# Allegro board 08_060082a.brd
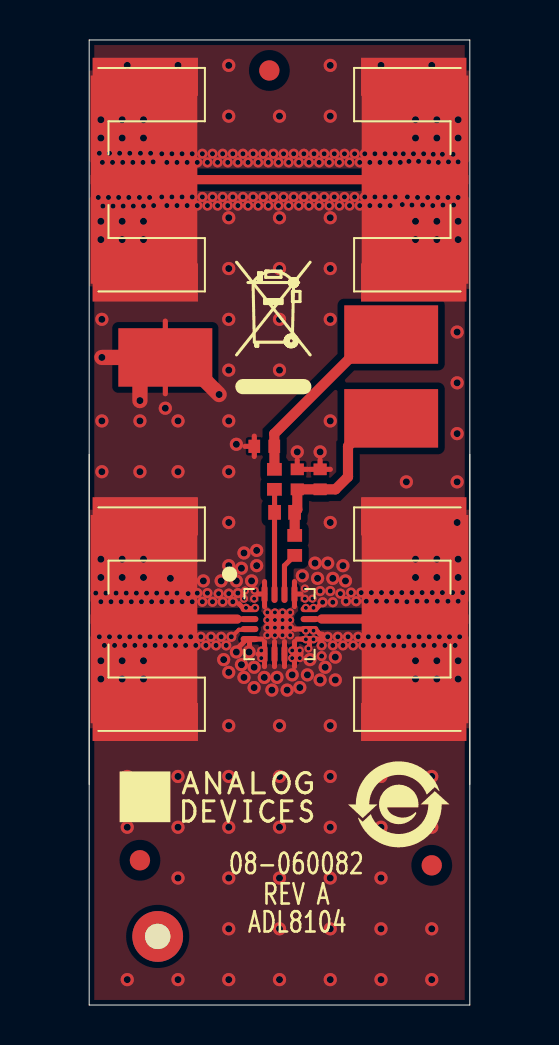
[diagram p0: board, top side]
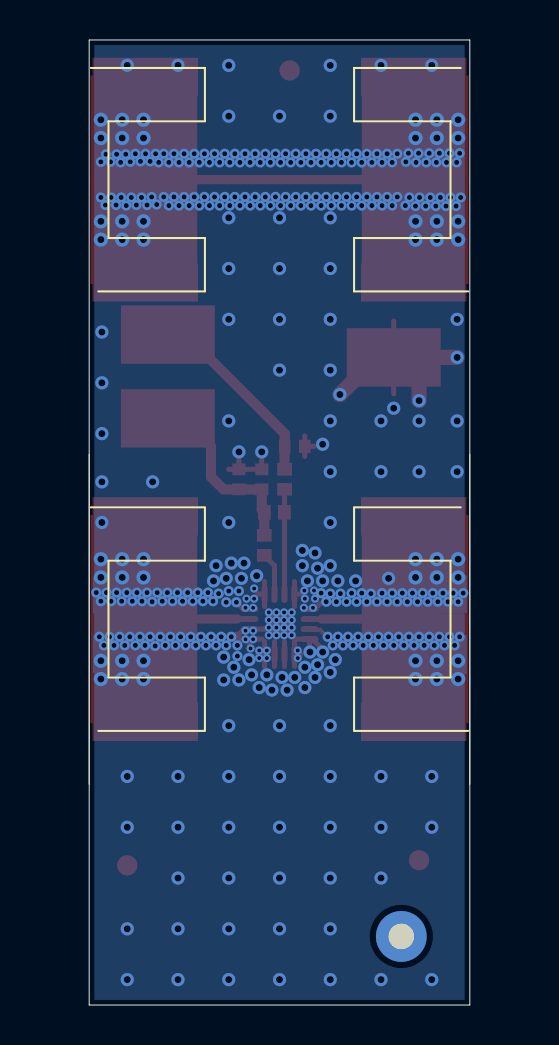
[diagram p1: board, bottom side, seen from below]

Outline 19.05 x 48.26 mm; copper layers: TOP, L2_GND, L3_GND, BOTTOM. Coordinates in mm from the lower left corner of the outline.
Outline path: 0,48.26 19.05,48.26 19.05,0 0,0 0,48.26

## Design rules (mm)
constraint set DEFAULT: min track width 0.254

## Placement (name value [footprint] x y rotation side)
C1  1000PF  [C0402]  11.56 26.29 90 top
C2  1uF  [C0402]  10.41 26.29 90 top
C3  1000PF  [C0402]  8.76 27.94 0 top
DUT1  GEN_QFN16_3x3_PAD1_1x1_1  [QFN16_3X3_PAD1_1X1_1]  9.53 19.05 270 top
GND  5016  [CNKEY5016TP]  3.81 32.39 0 top
J1  142-0701-851  [CNSMA10G62THK_EDGE]  0 41.28 180 top
J2  142-0701-851  [CNSMA10G62THK_EDGE]  19.05 41.28 0 top
NOREF  -  []  -219.07 -158.75 0 top
NOREF#2  -  []  0 0 0 top
NOREF#3  -  [unnamed#2]  9.02 46.74 0 top
NOREF#4  -  []  9.02 30.61 0 top
NOREF#5  -  []  161.93 69.85 0 top
NOREF#6  -  []  63.5 63.5 0 top
NOREF#7  -  [unnamed#2]  17.15 6.99 0 top
NOREF#8  -  []  -219.07 -158.75 0 top
NOREF#9  -  []  -89.66 126.66 0 top
NOREF#10  -  []  0 18.92 0 top
NOREF#11  -  []  -269.88 -336.55 0 top
NOREF#12  -  []  -192.3 79.27 0 top
NOREF#13  -  []  -269.88 -336.55 0 top
NOREF#14  -  [unnamed#2]  3.43 3.43 0 top
NOREF#15  -  []  12.32 61.09 0 top
NOREF#16  -  []  0 0 0 top
NOREF#17  -  []  19.05 0 90 top
NOREF#18  -  []  -99.9 133.05 0 top
NOREF#19  -  []  0 0 90 top
NOREF#20  -  []  -203.45 -70.99 0 top
NOREF#21  -  []  0 0 0 top
NOREF#22  -  [unnamed#2]  2.54 7.24 0 top
NOREF#23  -  []  52.7 -150.24 0 top
NOREF#24  -  []  0 48.26 270 top
NOREF#25  -  []  1.52 9.14 0 top
NOREF#26  -  []  19.05 0 90 top
NOREF#27  -  []  19.05 48.26 180 top
NOREF#28  -  []  15.49 10.03 0 top
NOREF#29  -  []  170.94 43.43 180 bottom
R1  0  [R0402]  9.27 26.29 270 top
R2  0  [R0402]  9.78 24.64 0 top
R4  0  [R0402]  10.29 22.99 270 top
RFIN  142-0701-851  [CNSMA10G62THK_EDGE]  0 19.3 180 top
RFOUT  142-0701-851  [CNSMA10G62THK_EDGE]  19.05 19.3 0 top
VBIAS  5016  [CNKEY5016TP]  15.11 33.53 0 top
VDD  5016  [CNKEY5016TP]  15.11 29.34 0 top

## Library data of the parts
C1 C3 = CAP: User Part Number: UPN; Tolerance: 10; alternate symbols: (); part number: CAP_SM-1000PF,25V,10,E025706,C0402; tolerance: 10
C2 = CAP: User Part Number: UPN; Tolerance: 10; alternate symbols: (); part number: CAP_SM-1UF,6.3V,10,E011561,C0402; tolerance: 10
DUT1 = GEN16P_SQ_PAD: User Part Number: UPN; Tolerance: N/A; alternate symbols: (); part number: GEN16P_SQ_PAD_SM-GEN_QFN16_3X3_PAD1_1X1_1,E007588,QFN16_3X3_PAD1_1X1_1; tolerance: N/A
GND VBIAS VDD = CNTP1P: alternate symbols: (); part number: CNTP1P_SM-5016,E005890,CNKEY5016TP; tolerance: N/A
J1 J2 RFIN RFOUT = CNBNC4P: User Part Number: UPN; Tolerance: N/A; alternate symbols: (CNSMA10G30THK_EDGE,CNSMA10G10THK_EDGE,CNSMAL562W375H166_HFSS); part number: CNBNC4P_SM-142-0701-851,E029168,CNSMA10G62THK_EDGE; tolerance: N/A
R1 R2 R4 = RES: User Part Number: UPN; Tolerance: 1; alternate symbols: (R0402L); part number: RES_SM-0,E010661,1/16W,1,R0402; tolerance: 1

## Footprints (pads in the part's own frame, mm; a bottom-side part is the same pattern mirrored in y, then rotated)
C0402
  rect 0.584x0.66 smd: 1(-0.5,0) 2(0.5,0)
CNKEY5016TP
  rect 4.699x2.921 smd: 1(0,0)
CNSMA10G62THK_EDGE
  rect 2.349x0.457 smd: 1(-1.252,0)
  custom 0.921x0.921 smd: 2(-2.807,-4.255) 3(-2.807,4.255)
  rect 5.334x10.414 smd: 4(-2.743,0)
QFN16_3X3_PAD1_1X1_1
  oval 0.305x0.889 smd: 1(-0.749,-1.501) 2(-0.249,-1.501) 3(0.249,-1.501) 4(0.749,-1.501) 9(0.749,1.501) 10(0.249,1.501) 11(-0.249,1.501) 12(-0.749,1.501)
  oval 0.889x0.305 smd: 5(1.501,-0.749) 6(1.501,-0.249) 7(1.501,0.249) 8(1.501,0.749) 13(-1.501,0.749) 14(-1.501,0.249) 15(-1.501,-0.249) 16(-1.501,-0.749)
  rect 1.092x1.092 smd: PAD(0,0)
R0402
  rect 0.635x0.737 smd: 1(-0.5,0) 2(0.5,0)
unnamed#2
  round 1.016 smd: (0,0)

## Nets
GND: C1.2(N2) C2.2(N2) C3.1 DUT1.1 DUT1.3 DUT1.4 DUT1.5 DUT1.6 DUT1.7 DUT1.8 DUT1.9 DUT1.10 DUT1.12 DUT1.13 DUT1.16 DUT1.PAD GND.1(N1) J1.2 J1.3 J1.4(SH3) J2.2 J2.3 J2.4(SH3) RFIN.2 RFIN.3 RFIN.4(SH3) RFOUT.2 RFOUT.3 RFOUT.4(SH3)
UNNAMED_3_CAP_I190_N1: C1.1 C2.1 R2.2(N2) R4.1 VDD.1(N1)
UNNAMED_3_CAP_I214_N2: C3.2(N2) R1.1 VBIAS.1(N1)
UNNAMED_3_CNBNC4P_I227_CNTR: DUT1.2 RFIN.1
UNNAMED_3_CNBNC4P_I228_CNTR: J1.1 J2.1
UNNAMED_3_CNBNC4P_I232_CNTR: DUT1.11 RFOUT.1
UNNAMED_3_GEN16PSQPAD_I213_N14: DUT1.14 R4.2(N2)
UNNAMED_3_GEN16PSQPAD_I213_N15: DUT1.15 R1.2(N2) R2.1

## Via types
v1: diameter 0.66, hole 0.356, TOP to BOTTOM, 116 vias
v2: diameter 0.711, hole 0.356, TOP to BOTTOM, 48 vias
v3: diameter 0.508, hole 0.254, TOP to BOTTOM, 257 vias
v4: diameter 0.406, hole 0.203, TOP to BOTTOM, 38 vias

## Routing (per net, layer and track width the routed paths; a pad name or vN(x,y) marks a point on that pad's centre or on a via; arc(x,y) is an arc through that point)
GND: length 33.2
  TOP w0.203: 7.13,18.41 7.49,18.77 7.99,18.77 DUT1.3
  TOP w0.254: 11.78,18.41 v3(11.94,18.41) ; DUT1.5 8.78,18.17 ; DUT1.5 8.78,16.92 ; DUT1.5 8.44,17.55 ; 8.02,17.97 DUT1.4 ; DUT1.4 8.65,18.3 ; DUT1.4 7.89,18.3 7.24,17.65 ; C1.2 11.56,27.26 ; C1.2 12.07,26.79 ; C1.2 11.05,26.79 ; 9.77,16.92 DUT1.7 9.77,18.17 ; 8.78,19.93 DUT1.16 ; DUT1.16 8.78,21.18 ; DUT1.16 8.44,20.55 ; DUT1.9 11.65,18.3 ; DUT1.9 10.4,18.3 ; DUT1.9 11.03,17.97 ; v3(11.68,20.14) 11.34,19.8 DUT1.12 ; 10.27,19.93 DUT1.13 ; DUT1.13 10.27,21.18 ; DUT1.13 10.61,20.55 ; 8.26,27.43 C3.1 ; C3.1 8.26,28.45 ; C3.1 7.79,27.94 ; DUT1.8 10.27,18.17 ; DUT1.8 10.27,16.92 ; DUT1.8 10.61,17.55 ; 10.29,18.8 10.29,18.8 DUT1.10 11.3,18.8 11.56,18.54 11.68,18.54 ; DUT1.1 7.76,19.8 7.49,20.07 ; 3.81,34.2 GND.1 3.81,30.57 ; 10.41,27.26 C2.2 10.92,26.79 ; 9.28,16.92 DUT1.6 9.28,18.17
  TOP w0.762: 2.54,32.39 GND.1 5.08,32.39 5.08,31.95 v1(6.5,30.53) ; 2.54,32.39 v1(2.54,30.23) ; 2.54,32.39 v1(0.64,32.39)
  vias: v1(0.64,34.29) v1(0.64,29.21) v1(0.64,26.67) v1(1.91,46.99) v1(1.91,11.43) v1(1.91,8.89) v1(1.91,1.27) v1(2.54,29.21) v1(2.54,26.67) v1(3.81,29.84) v1(4.06,21.34) v1(4.45,46.99) v1(4.45,29.21) v1(4.45,26.67) v1(4.45,11.43) v1(4.45,8.89) v1(4.45,6.35) v1(4.45,1.27) v1(5.72,21.21) v1(6.6,21.21) v1(6.73,17.27) v1(6.99,46.99) v1(6.99,44.45) v1(6.99,39.37) v1(6.99,36.83) v1(6.99,34.29) v1(6.99,31.75) v1(6.99,29.21) v1(6.99,26.67) v1(6.99,24.13) v1(6.99,21.97) v1(6.99,16.64) v1(6.99,13.97) v1(6.99,11.43) v1(6.99,8.89) v1(6.99,6.35) v1(6.99,3.81) v1(6.99,1.27) v1(7.37,28.04) v1(7.37,21.21) v1(7.37,17.65) v1(7.62,21.84) v1(7.62,17.02) v1(7.75,22.61) v1(7.75,16.38) v1(8,17.65) v1(8.13,21.21) v1(8.26,16.89) v1(8.26,15.88) v1(8.38,22.73) v1(8.38,21.97) v1(8.76,16.38) v1(9.14,15.75) v1(9.4,16.38) v1(9.53,44.45) v1(9.53,39.37) v1(9.53,36.83) v1(9.53,34.29) v1(9.53,31.75) v1(9.53,13.97) v1(9.53,11.43) v1(9.53,8.89) v1(9.53,6.35) v1(9.53,3.81) v1(9.53,1.27) v1(9.91,15.75) v1(10.16,16.51) v1(10.41,27.66) v1(10.54,15.88) v1(10.67,21.46) v1(10.92,16.51) v1(11.05,17.27) v1(11.3,22.1) v1(11.43,21.34) v1(11.56,27.66) v1(11.56,16.26) v1(11.81,16.89) v1(11.94,22.1) v1(12.07,46.99) v1(12.07,44.45) v1(12.07,39.37) v1(12.07,36.83) v1(12.07,34.29) v1(12.07,29.21) v1(12.07,24.13) v1(12.07,13.97) v1(12.07,11.43) v1(12.07,8.89) v1(12.07,6.35) v1(12.07,3.81) v1(12.07,1.27) v1(12.19,21.34) v1(12.32,17.4) v1(12.32,16.26) v1(12.7,21.97) v1(12.83,21.21) v1(14.61,46.99) v1(14.61,11.43) v1(14.61,8.89) v1(14.61,6.35) v1(14.61,3.81) v1(14.61,1.27) v1(15.88,26.16) v1(17.15,46.99) v1(17.15,11.43) v1(17.15,8.89) v1(17.15,3.81) v1(17.15,1.27) v1(18.42,33.66) v1(18.42,31.12) v1(18.42,28.58) v1(18.42,26.16) v1(18.42,24.13) v2(0.58,44.27) v2(0.58,43.36) v2(0.58,39.19) v2(0.58,38.28) v2(0.58,22.3) v2(0.58,21.38) v2(0.58,17.22) v2(0.58,16.3) v2(1.65,44.27) v2(1.65,43.36) v2(1.65,39.19) v2(1.65,38.28) v2(1.65,22.3) v2(1.65,21.38) v2(1.65,17.22) v2(1.65,16.3) v2(2.72,44.27) v2(2.72,43.36) v2(2.72,39.19) v2(2.72,38.28) v2(2.72,22.3) v2(2.72,21.38) v2(2.72,17.22) v2(2.72,16.3) v2(16.33,44.27) v2(16.33,43.36) v2(16.33,39.19) v2(16.33,38.28) v2(16.33,22.3) v2(16.33,21.38) v2(16.33,17.22) v2(16.33,16.3) v2(17.4,44.27) v2(17.4,43.36) v2(17.4,39.19) v2(17.4,38.28) v2(17.4,22.3) v2(17.4,21.38) v2(17.4,17.22) v2(17.4,16.3) v2(18.47,44.27) v2(18.47,43.36) v2(18.47,39.19) v2(18.47,38.28) v2(18.47,22.3) v2(18.47,21.38) v2(18.47,17.22) v2(18.47,16.3) v3(0.33,20.6) v3(0.46,40.39) v3(0.51,42.6) v3(0.51,18.41) v3(0.66,42.14) v3(0.58,20.17) v3(0.69,39.95) v3(0.76,17.98) v3(0.84,20.6) v3(0.97,40.39) v3(1.02,42.6) v3(1.02,18.41) v3(1.17,42.14) v3(1.09,20.17) v3(1.19,39.95) v3(1.27,17.98) v3(1.35,20.6) v3(1.47,40.39) v3(1.52,42.6) v3(1.52,18.41) v3(1.6,20.17) v3(1.68,42.14) v3(1.7,39.95) v3(1.85,20.6) v3(1.78,17.98) v3(2.03,42.6) v3(1.98,40.39) v3(2.03,18.41) v3(2.11,20.17) v3(2.18,42.14) v3(2.21,39.95) v3(2.36,20.6) v3(2.29,17.98) v3(2.57,42.6) v3(2.51,40.39) v3(2.54,18.41) v3(2.62,20.17) v3(2.69,42.14) v3(2.72,39.95) v3(2.87,20.6) v3(2.79,17.98) v3(3.07,42.6) v3(3.02,40.39) v3(3.05,18.41) v3(3.12,20.17) v3(3.2,42.16) v3(3.23,39.98) v3(3.3,17.98) v3(3.38,20.6) v3(3.56,18.41) v3(3.63,42.57) v3(3.63,40.41) v3(3.63,20.17) v3(3.81,17.98) v3(3.89,42.14) v3(3.89,39.98) v3(3.89,20.6) v3(4.06,18.41) v3(4.14,42.57) v3(4.14,40.41) v3(4.14,20.17) v3(4.32,17.98) v3(4.39,42.14) v3(4.39,39.98) v3(4.39,20.6) v3(4.57,18.41) v3(4.65,42.57) v3(4.65,40.41) v3(4.65,20.17) v3(4.83,17.98) v3(4.9,42.14) v3(4.9,39.98) v3(4.95,20.57) v3(5.16,42.57) v3(5.16,40.41) v3(5.16,20.17) v3(5.08,18.41) v3(5.33,17.98) v3(5.41,42.14) v3(5.41,39.98) v3(5.41,20.6) v3(5.66,42.57) v3(5.66,40.41) v3(5.66,20.17) v3(5.59,18.41) v3(5.84,17.98) v3(5.92,42.14) v3(5.92,39.98) v3(5.92,20.6) v3(6.17,42.57) v3(6.17,40.41) v3(6.17,20.17) v3(6.1,18.41) v3(6.35,17.98) v3(6.43,42.14) v3(6.43,39.98) v3(6.48,20.57) v3(6.6,18.41) v3(6.68,42.57) v3(6.68,40.41) v3(6.68,20.17) v3(6.86,17.98) v3(6.93,42.14) v3(6.93,39.98) v3(6.99,20.57) v3(7.11,18.41) v3(7.19,42.57) v3(7.19,40.41) v3(7.19,20.17) v3(7.44,42.14) v3(7.44,39.98) v3(7.44,20.6) v3(7.7,42.57) v3(7.7,40.41) v3(7.95,42.14) v3(7.95,39.98) v3(8.2,42.57) v3(8.2,40.41) v3(8.46,42.14) v3(8.46,39.98) v3(8.71,42.57) v3(8.71,40.41) v3(8.97,42.14) v3(8.97,39.98) v3(9.22,42.57) v3(9.22,40.41) v3(9.47,42.14) v3(9.47,39.98) v3(9.73,42.57) v3(9.73,40.41) v3(9.98,42.14) v3(9.98,39.98) v3(10.24,42.57) v3(10.24,40.41) v3(10.49,42.14) v3(10.49,39.98) v3(10.74,42.57) v3(10.74,40.41) v3(11,42.14) v3(11,39.98) v3(11.25,42.57) v3(11.25,40.41) v3(11.51,42.14) v3(11.51,39.98) v3(11.56,20.7) v3(11.63,17.98) v3(11.63,17.45) v3(11.76,42.57) v3(11.76,40.41) v3(12.01,42.14) v3(12.01,39.98) v3(12.07,20.7) v3(12.27,42.57) v3(12.27,40.41) v3(12.19,20.14) v3(12.19,17.98) v3(12.45,18.41) v3(12.52,42.14) v3(12.52,39.98) v3(12.57,20.57) v3(12.7,17.98) v3(12.78,42.57) v3(12.78,40.41) v3(12.85,20.19) v3(12.95,18.41) v3(13.03,42.14) v3(13.03,39.98) v3(13.11,20.62) v3(13.21,17.98) v3(13.28,42.57) v3(13.28,40.41) v3(13.36,20.19) v3(13.46,18.41) v3(13.54,42.14) v3(13.54,39.98) v3(13.61,20.62) v3(13.72,17.98) v3(13.79,42.57) v3(13.79,40.41) v3(13.87,20.19) v3(13.97,18.41) v3(14.05,42.14) v3(14.05,39.98) v3(14.12,20.62) v3(14.22,17.98) v3(14.3,42.57) v3(14.3,40.41) v3(14.38,20.19) v3(14.55,42.14) v3(14.55,39.98) v3(14.48,18.41) v3(14.63,20.62) v3(14.73,17.98) v3(14.81,42.57) v3(14.81,40.41) v3(14.88,20.19) v3(15.06,42.14) v3(15.06,39.98) v3(14.99,18.41) v3(15.14,20.62) v3(15.24,17.98) v3(15.32,42.57) v3(15.32,40.41) v3(15.39,20.19) v3(15.57,42.14) v3(15.49,18.41) v3(15.67,40.03) v3(15.65,20.62) v3(15.72,42.57) v3(15.75,17.96) v3(15.93,40.41) v3(15.9,20.17) v3(16,42.19) v3(16,18.41) v3(16.15,40) v3(16.15,20.62) v3(16.23,42.57) v3(16.26,17.98) v3(16.43,40.39) v3(16.41,20.19) v3(16.48,42.19) v3(16.51,18.41) v3(16.66,20.62) v3(16.74,42.57) v3(16.69,40) v3(16.74,17.98) v3(16.94,40.39) v3(16.89,20.19) v3(16.99,42.16) v3(17.02,18.41) v3(17.17,20.62) v3(17.22,42.55) v3(17.2,39.98) v3(17.27,17.98) v3(17.45,40.39) v3(17.42,20.19) v3(17.48,42.14) v3(17.53,18.41) v3(17.68,42.55) v3(17.7,40) v3(17.68,20.62) v3(17.81,17.98) v3(17.96,40.39) v3(17.96,20.19) v3(17.98,42.16) v3(18.03,18.41) v3(18.21,42.55) v3(18.24,40) v3(18.19,20.62) v3(18.31,17.98) v3(18.47,42.16) v3(18.47,40.39) v3(18.47,20.19) v3(18.54,18.41) v3(18.69,20.62) v4(7.75,20.32) v4(7.8,20.73) v4(7.85,19.86) v4(8.26,20.32) v4(8.28,20.73) v4(8.31,19.86) v4(8.61,17.73) v4(8.61,17.35) v4(8.92,19.63) v4(8.92,19.25) v4(8.92,18.87) v4(8.92,18.49) v4(9.3,19.63) v4(9.3,19.25) v4(9.3,18.87) v4(9.3,18.49) v4(9.68,19.63) v4(9.68,19.25) v4(9.68,18.87) v4(9.68,18.49) v4(10.06,19.63) v4(10.06,19.25) v4(10.06,18.87) v4(10.06,18.49) v4(10.16,17.73) v4(10.16,17.35) v4(10.54,17.73) v4(10.54,17.35) v4(10.8,20.83) v4(10.8,20.32) v4(10.85,19.86) v4(10.85,18.72) v4(10.85,18.29) v4(10.97,17.83) v4(11.18,20.32) v4(11.23,19.86) v4(11.23,18.72) v4(11.23,18.29)
UNNAMED_3_CAP_I190_N1: length 9.4
  TOP w0.508: VDD.1 14.35,29.34 12.95,27.94 12.95,26.42 12.33,25.79 C1.1 C2.1 10.41,24.77 R2.2 10.29,24.63 R4.1
UNNAMED_3_CAP_I214_N2: length 9.7
  TOP w0.508: R1.1 9.27,27.93 C3.2 9.26,28.57 14.22,33.53 VBIAS.1
UNNAMED_3_CNBNC4P_I227_CNTR: length 6.8
  TOP w0.254: 7.41,19.3 DUT1.2
  TOP w0.457: RFIN.1 7.41,19.3
UNNAMED_3_CNBNC4P_I228_CNTR: length 16.5
  TOP w0.457: J1.1 J2.1
UNNAMED_3_CNBNC4P_I232_CNTR: length 6.8
  TOP w0.254: 11.63,19.3 DUT1.11
  TOP w0.457: 11.63,19.3 17.79,19.3 RFOUT.1
UNNAMED_3_GEN16PSQPAD_I213_N14: length 2.1
  TOP w0.254: R4.2 9.77,21.97 DUT1.14
UNNAMED_3_GEN16PSQPAD_I213_N15: length 5.2
  TOP w0.254: DUT1.15 9.28,24.64 R2.1 9.28,25.78 R1.2

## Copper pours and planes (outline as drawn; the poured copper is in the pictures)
GND on TOP: 0.25,0.25 0.25,13.84 0,13.84 0,24.77 0.25,24.77 0.25,35.94 0,35.94 0,46.74 0.25,46.74 0.25,48.01 18.8,48.01 18.8,46.74 19.05,46.74 19.05,35.81 18.8,35.81 18.8,24.77 19.05,24.77 19.05,13.84 18.8,13.84 18.8,0.25
GND on BOTTOM: 0.25,0.25 0.25,16.54 0.15,16.54 0.15,18.49 1.63,18.49 1.63,18.57 0.25,18.57 0.25,19.58 1.55,19.58 1.55,19.61 0.15,19.61 0.15,21.49 0.25,21.49 0.25,48.01 18.8,48.01 18.8,21.39 18.87,21.39 18.87,19.58 18.8,19.58 18.8,18.52 18.87,18.52 18.87,16.61 18.8,16.61 18.8,0.25
GND on L2_GND, L3_GND: 0.25,0.25 0.25,14.86 0,14.86 0,23.75 0.25,23.75 0.25,39.12 0,39.12 0,48.01 19.05,48.01 19.05,39.12 18.8,39.12 18.8,23.75 19.05,23.75 19.05,14.86 18.8,14.86 18.8,0.25

Small or netless copper shapes (teardrops, artwork), in the pictures only: 1 on TOP

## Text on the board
Ref Des/Silkscreen Top: 08-060082 | REV A | ADL8104
DIMENSION: EDGE PLATING | 4 PLACES | SEE DETAIL A AND NOTE 17 | SEE NOTE 15 | MAX
BODY_CENTER: ROGERS 4350B 10 MIL | 17.    EDGE PLATING TO CONNECT OUTER AND INTERNAL GROUND LAYERS FOR THE | WIDTH OF THE CONNECTORS.
User.15: AUTO-HANDLER ENGINEERING INPUT | REFERENCE/EVALUATION DESIGN: | Previous designs can provide guidance in the layout of the board. or provide | a starting point to note differences. | MAXIMUM FREQUENCIES: | RF net frequencies will determine the connectors to use. | ARE THRU CAL NETS required? | MAXIMUM CURRENT REQUIREMENTS of voltage nets. | COMMUNICATE: | Review anticipated stack-up, materials, trace/space/mask for RF, stiffener, | etch matching, edge plating, via fill, etc. | CONNECTOR SELECTION: | Given a max frequency any connector of that rating or above may be selected. | The lower frequency connectors are generally lower cost and are usually easier | to install. A mix of RF connectors is allowed. | STIFFENER SELECTION: (Allegro symbol prefix adch_plate...) | M025215 adch_plate_hf_ext_cassini_03-052988.bsm (Plus future flange mount designs) | Is used with the flanged RF connectors cnsma19g_flange and cnsma30g_flange. | The 19g connector, board thickness of .032 +/-10% or less and up to 4 layers. | The 20-30g connector, uses a 10mil core or less dielectric and has 2 layers. | The board outline is to match this plate outline. Bottom layer is to be ground. | M024984 adch_plate_hf_ext_cassini_03-052985.bsm (Plus future non flange mount) | Is used with any of the frequency listed RF edge connectors for 62 thick boards. | Board thickness is to be .062 +/- 10%, with 4 or more layers. Bottom layer is | to be ground. The board outline at a minimum must cover the plate outline, and | is to be expanded to allow for the placement of the RF connectors in an area | clear of the contactor, handler arm arc, and the stiffener plate. | PLACEMENT AND ROUTING CONSIDERATIONS: | The autohandler plate is to be placed mirrored at X=0 Y=0 zero rotation.(per notes) | The Ismeca_handler_ko.bsm Is to be placed at X=0 Y=0 zero rotation. | The contactor to be specified by manufacturing engineering in the HLM Forum. | Locate contactor at X=0 Y=0 rotated to have pin 1 to the upper left (NW quadrant.) | To mount flanged RF connectors first display Package Geometry/Referance and | /Assembly Bottom. Place each at a center circle (with the cross) of a three circle | mounting hole pattern indicator. Orient to cover the outside reference pattern | circles. Choose the location that makes the shortest RF connection or if part of a | matched RF pair choose the circles that accomodate the best matching trace pattern. | Locate RF edge launch connectors at points that allow for clean short routing that | clears the contactor boundary, Ismecca_handler_ko, and the autohandler stiffener. | Their placement should consider matched length requirements that does not encroach | on the contactor arms having via fencing along their sides. Keep in mind that the | connector outline edges will have to incorporate into the Board Geometry/Outline. | RF ROUTING, Use the material, trace width and space in the connector symbol notes. | Layout pattern should resemble that of the respective EVAL board layout. | RF lines ideally to be symmetrical, straight and as short as possible. Neck down to | IC pad width as close to pin as possible. Pad stacks on RF trace may be adjusted | to the width of the RF trace if less than 10 mils, otherwise add fillets. | Curves on RF lines require a minimum radius 3 times the trace width. | (Greater than 3X is preferred.) | GND-VIA fence to be along each side of RF lines, via edge to be close to the GND | plane edge. Do not encroach into the etch to trace spacing. | Continuous GND edge is desired along RF paths, keep RF to RF and RF to DC lines | separated by GND if possible. Connect GND pins adjacent to RF pins to GND plane. | THRU CAL NETS:Are they required? How is their length to be determined? | The default is CAL lines will have the same components mounted at the same | intervals as the RF trace it represents. (Ideally copy the full trace component | and via structure, and swap in the through cal components.) | DC TRACES: Non critical signal trace width is typically 10mils. | Voltages are preferably in planes, if routed they must be sized to handle the | maximum current requirements. (Search web "PCB current capacity calculator") | VIAS: GND within pads use VIA2510 other signal power and ground use VIA2814. | Blind and burried vias also to have 14 drill and 28 pad. Filled vias are not | recommended for Auto-handler designs. Shape connection to be full contact. | If thru non GND signal vias are used, they are to be covered by bottom side solder- | mask (pad+2x gap+10mils min.). Unless these vias are on a 62 mil board and the via | is more than 20 mils away from the stiffener plate. | (A positive bottom mask may need to be generated.) | CONNECTOR NAMING | CONNECTOR TYPE | FREQUENCY | PREFIX | CNSMA20G62THK_EDGE | MOUNTING FORM | BOARD THICKNESS | GND AND POWER PLANES: | Add ground pour to all non power plane layers. Take care not to create thin ground | shapes between signals without vias on the top layer that will act as antena. | GND planes for the width of the edge connectors to be 3 mils from the outline, | unless the connector specifies edge plating is required. Signals and planes in all | other areas to be 10 mil minimum from board outline. | Thermal relief for edge connector GND pins and all Dut pins to be full contact. | Thermal relief for other pins to be a nominal 10 mils by 4 spokes, adjustments may | be made for pins with less spokes. | STIFFENER | 03-052988 | 03-052985 | STACKUP | 2_LYR6-6R4350B | 2_LYR10R4350B | 4_LYR10R4350B-T0P | THICKNESS | ~9MILS | ~12MILS | <32MILS +/- 10% | 62MILS +/-10% | CONNECTOR/FREQUENCY | CNSMA30G_FLANGE | CNSMA19G_FLANGE | CNSMA10G62THK_EDGE | CNK38G62THK_EDGE | CNK40G62THK_EDGE | CN2_4MM50G62THK_EDGE | CN2_4MM50G62THK_LP_EDGE
User.18: LYR2 GND | 08-      -07
User.19: LYR3 GND | 08-      -08
User.23: H.NGUYEN | 01NOV19 | H.N.
User.32: FIGURE | SIZE | 8.0 | 10.0 | 14.0 | 50.0 | PLATED | NON-PLATED | FINISHED HOLES IN MILS | ALL UNITS ARE IN MILS | QTY | 38 | 257 | 48 | 116 | 1 | TOLERANCE/NOTES
